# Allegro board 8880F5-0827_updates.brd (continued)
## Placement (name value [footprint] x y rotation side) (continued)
NOREF#692  -  []  277.17 288.86 0 top
NOREF#693  -  []  272.24 242.32 90 top
NOREF#694  -  []  118.99 171.65 0 top
NOREF#695  -  []  341.63 195.43 90 top
NOREF#696  -  []  310.43 188.88 0 top
NOREF#697  -  []  390.53 180.15 0 top
NOREF#698  -  []  326.23 233.13 0 top
NOREF#699  -  []  420.15 131.44 90 top
NOREF#700  -  []  352.25 182.96 0 top
NOREF#701  -  []  251.62 204.35 90 top
NOREF#702  -  []  405.93 256.92 90 top
NOREF#703  -  []  385.19 289.12 0 top
NOREF#704  -  []  501.87 276.41 90 top
NOREF#705  -  []  310.41 186.34 90 top
NOREF#706  -  []  199.59 216.47 90 top
NOREF#707  -  []  106.11 234.24 0 top
NOREF#708  -  []  229.51 246.66 0 top
NOREF#709  -  []  384.17 180.15 90 top
NOREF#710  -  []  182.57 171.96 0 top
NOREF#711  -  []  262.36 225.04 90 top
NOREF#712  -  []  201.23 229.07 90 top
NOREF#713  -  []  221.56 239.06 0 top
NOREF#714  -  []  389.7 209.36 0 top
NOREF#715  -  []  401.89 180.15 0 top
NOREF#716  -  []  265.81 296.86 0 top
NOREF#717  -  []  259.97 204.35 90 top
NOREF#718  -  []  259.33 264.35 90 top
NOREF#719  -  []  465.45 273.87 90 top
NOREF#720  -  []  423.61 182.42 90 top
NOREF#721  -  []  238.3 223.52 90 top
NOREF#722  -  []  346.69 128.87 90 top
NOREF#723  -  []  199.33 226.57 90 top
NOREF#724  -  []  352.25 185.5 0 top
NOREF#725  -  []  209.33 187.82 90 top
NOREF#726  -  []  219.81 213.69 90 top
NOREF#727  -  []  127.55 191.95 90 top
NOREF#728  -  []  380.59 287.22 0 top
NOREF#729  -  []  451.68 186.77 0 top
NOREF#730  -  []  221.56 242.89 0 top
NOREF#731  -  []  328.96 224.72 0 top
NOREF#732  -  []  331.06 223.82 90 top
NOREF#733  -  []  336.77 225.04 90 top
NOREF#734  -  []  192.57 256.4 90 top
NOREF#735  -  []  319.33 243.63 90 top
NOREF#736  -  []  340.61 286.96 90 top
NOREF#737  -  []  310.41 187.61 90 top
NOREF#738  -  []  384.36 131.89 0 top
NOREF#739  -  []  383.09 241.11 0 top
NOREF#740  -  []  395.07 129.99 0 top
NOREF#741  -  []  337.09 224.74 90 top
NOREF#742  -  []  310.43 254.01 0 top
NOREF#743  -  []  258.2 246.67 0 top
NOREF#744  -  []  184.47 165.4 90 top
NOREF#745  -  []  369.63 289.12 0 top
NOREF#746  -  []  168.13 240.88 90 top
NOREF#747  -  []  210.6 255.9 90 top
NOREF#748  -  []  317.05 288.86 0 top
NOREF#749  -  []  448.94 276.41 90 top
NOREF#750  -  []  465.45 290.38 90 top
NOREF#751  -  []  473.79 239.64 0 top
NOREF#752  -  []  226.85 271.67 0 top
NOREF#753  -  []  201.23 206.29 90 top
NOREF#754  -  []  304.65 271.67 0 top
NOREF#755  -  []  369.38 257.11 0 top
NOREF#756  -  []  332.51 264.35 90 top
NOREF#757  -  []  373.87 171.39 0 top
NOREF#758  -  []  392.47 224.3 90 top
NOREF#759  -  []  327.25 204.35 90 top
NOREF#760  -  []  396.28 180.2 90 top
NOREF#761  -  []  314.33 228.13 90 top
NOREF#762  -  []  309.05 211.67 0 top
NOREF#763  -  []  314.33 168.13 90 top
NOREF#764  -  []  240.83 254.63 0 top
NOREF#765  -  []  459.28 211.76 0 top
NOREF#766  -  []  175.8 187.82 90 top
NOREF#767  -  []  107.02 171.57 0 top
NOREF#768  -  []  333.4 264.35 90 top
NOREF#769  -  []  111.54 290.38 90 top
NOREF#770  -  []  333.4 204.35 90 top
NOREF#771  -  []  424.47 163.09 90 top
NOREF#772  -  []  246.23 173.13 0 top
NOREF#773  -  []  336.77 165.04 90 top
NOREF#774  -  []  412.24 144.98 90 top
NOREF#775  -  []  209.23 250.38 90 top
NOREF#776  -  []  374.34 210.38 90 top
NOREF#777  -  []  271.04 242.96 0 top
NOREF#778  -  []  407.71 217.61 0 top
NOREF#779  -  []  318.3 163.52 90 top
NOREF#780  -  []  175.7 154.88 90 top
NOREF#781  -  []  184.47 231.27 90 top
NOREF#782  -  []  346.27 135.17 90 top
NOREF#783  -  []  263.19 135.19 0 top
NOREF#784  -  []  409.74 180.2 90 top
NOREF#785  -  []  453.88 195.91 0 top
NOREF#786  -  []  175.8 174.36 90 top
NOREF#787  -  []  230.43 189.52 0 top
NOREF#788  -  []  230.41 193.37 90 top
NOREF#789  -  []  337.09 223.52 90 top
NOREF#790  -  []  326.17 131.69 90 top
NOREF#791  -  []  373.68 265.11 0 top
NOREF#792  -  []  259.33 205.55 0 top
NOREF#793  -  []  166.06 230.19 90 top
NOREF#794  -  []  184.89 240.88 90 top
NOREF#795  -  []  450.03 225.6 0 top
NOREF#796  -  []  478.57 257.36 90 top
NOREF#797  -  []  409.74 163.69 90 top
NOREF#798  -  []  237.57 209.63 90 top
NOREF#799  -  []  293.66 272.15 90 top
NOREF#800  -  []  313.98 131.09 90 top
NOREF#801  -  []  262.68 224.74 90 top
NOREF#802  -  []  229.51 247.93 0 top
NOREF#803  -  []  211.11 173.86 90 top
NOREF#804  -  []  167.7 255.15 90 top
NOREF#805  -  []  103.93 235.64 90 top
NOREF#806  -  []  84.04 290.38 90 top
NOREF#807  -  []  209.23 209.49 90 top
NOREF#808  -  []  315.16 290.13 90 top
NOREF#809  -  []  383.09 224.85 0 top
NOREF#810  -  []  298.49 288.91 90 top
NOREF#811  -  []  301.56 179.06 0 top
NOREF#812  -  []  318.3 224.74 90 top
NOREF#813  -  []  302.11 252.14 0 top
NOREF#814  -  []  459.28 183.57 90 top
NOREF#815  -  []  381.74 232.85 0 top
NOREF#816  -  []  177.33 242.18 90 top
NOREF#817  -  []  281.47 296.86 0 top
NOREF#818  -  []  378.33 257.11 90 top
NOREF#819  -  []  288.14 286.96 0 top
NOREF#820  -  []  459.28 227 0 top
NOREF#821  -  []  167.7 229.07 90 top
NOREF#822  -  []  257.09 223.52 90 top
NOREF#823  -  []  192.47 236.67 90 top
NOREF#824  -  []  397.8 146.33 90 top
NOREF#825  -  []  386.46 139.89 0 top
NOREF#826  -  []  463.61 222.58 0 top
NOREF#827  -  []  318.32 131.64 0 top
NOREF#828  -  []  310.43 193.37 90 top
NOREF#829  -  []  409.49 163.64 0 top
NOREF#830  -  []  398.65 273.11 0 top
NOREF#831  -  []  376.98 224.6 0 top
NOREF#832  -  []  417.2 171.64 0 top
NOREF#833  -  []  253.4 265.56 90 top
NOREF#834  -  []  192.47 264.1 90 top
NOREF#835  -  []  272.25 183.59 90 top
NOREF#836  -  []  271.04 189.18 0 top
NOREF#837  -  []  369.63 273.11 0 top
NOREF#838  -  []  296.96 252.14 0 top
NOREF#839  -  []  263.71 288.86 0 top
NOREF#840  -  []  392.24 199.18 90 top
NOREF#841  -  []  460.93 182.17 90 top
NOREF#842  -  []  184.47 190.12 90 top
NOREF#843  -  []  256.73 132.14 0 top
NOREF#844  -  []  406.52 131.89 90 top
NOREF#845  -  []  184.47 242.78 90 top
NOREF#846  -  []  115.61 191.95 0 top
NOREF#847  -  []  311.44 288.86 0 top
NOREF#848  -  []  182.57 254 0 top
NOREF#849  -  []  296.81 275.94 0 top
NOREF#850  -  []  461.96 210.36 0 top
NOREF#851  -  []  172.08 275.14 90 top
NOREF#852  -  []  175.7 148.38 90 top
NOREF#853  -  []  339.33 205.56 0 top
NOREF#854  -  []  277.5 155.38 0 top
NOREF#855  -  []  371.48 232.6 0 top
NOREF#856  -  []  248.61 290.13 90 top
NOREF#857  -  []  116.01 214.71 0 top
NOREF#858  -  []  184.47 217.55 90 top
NOREF#859  -  []  419.9 240.66 90 top
NOREF#860  -  []  184.47 186.57 0 top
NOREF#861  -  []  237.83 257.63 0 top
NOREF#862  -  []  424.98 146.33 90 top
NOREF#863  -  []  465.81 171.53 0 top
NOREF#864  -  []  468.68 129.54 0 top
NOREF#865  -  []  393.19 287.22 90 top
NOREF#866  -  []  396.55 257.37 0 top
NOREF#867  -  []  276.4 147.38 0 top
NOREF#868  -  []  168.13 159.1 90 top
NOREF#869  -  []  209.33 228.97 90 top
NOREF#870  -  []  215.96 248.49 0 top
NOREF#871  -  []  332.83 265.86 90 top
NOREF#872  -  []  326.23 173.13 0 top
NOREF#873  -  []  260.74 135.19 90 top
NOREF#874  -  []  377.48 273.16 90 top
NOREF#875  -  []  383.07 163.44 90 top
NOREF#876  -  []  318.45 197.01 0 top
NOREF#877  -  []  404.15 289.12 0 top
NOREF#878  -  []  167.7 247.18 90 top
NOREF#879  -  []  425.2 161.74 90 top
NOREF#880  -  []  118.74 210.19 90 top
NOREF#881  -  []  352.24 189.18 90 top
NOREF#882  -  []  330.49 163.52 90 top
NOREF#883  -  []  201.23 187.92 90 top
NOREF#884  -  []  247.78 140.14 0 top
NOREF#885  -  []  36.1 129.71 90 top
NOREF#886  -  []  384.36 131.89 0 top
NOREF#887  -  []  201.21 276.04 90 top
NOREF#888  -  []  373.83 192.28 0 top
NOREF#889  -  []  128.05 271.33 90 top
NOREF#890  -  []  405.93 224.56 90 top
NOREF#891  -  []  119.7 231.22 0 top
NOREF#892  -  []  272.25 189.82 0 top
NOREF#893  -  []  155.57 289.11 90 top
NOREF#894  -  []  256.45 164.74 0 top
NOREF#895  -  []  247.25 205.56 90 top
NOREF#896  -  []  298.16 248.49 0 top
NOREF#897  -  []  268.94 272.1 0 top
NOREF#898  -  []  272.24 189.18 90 top
NOREF#899  -  []  352.55 241.37 0 top
NOREF#900  -  []  419.9 240.56 90 top
NOREF#901  -  []  274.37 147.93 90 top
NOREF#902  -  []  309.05 271.67 0 top
NOREF#903  -  []  258.2 186.67 0 top
NOREF#904  -  []  253.53 140.14 0 top
NOREF#905  -  []  250.5 288.86 0 top
NOREF#906  -  []  247.57 264.65 90 top
NOREF#907  -  []  385.93 178.25 0 top
NOREF#908  -  []  309.21 193.37 0 top
NOREF#909  -  []  318.45 257.01 0 top
NOREF#910  -  []  167.7 163.2 90 top
NOREF#911  -  []  329.85 164.72 0 top
NOREF#912  -  []  351.04 245.5 0 top
NOREF#913  -  []  410.52 273.37 0 top
NOREF#914  -  []  418.12 257.42 90 top
NOREF#915  -  []  410.52 241.11 0 top
NOREF#916  -  []  306.71 131.64 0 top
NOREF#917  -  []  410.84 163.64 90 top
NOREF#918  -  []  343.31 164.74 0 top
NOREF#919  -  []  459.28 192.71 0 top
NOREF#920  -  []  392.73 171.64 0 top
NOREF#921  -  []  383.01 139.89 0 top
NOREF#922  -  []  199.33 185.42 0 top
NOREF#923  -  []  11.6 261.68 90 top
NOREF#924  -  []  331.86 252.43 90 top
NOREF#925  -  []  248.33 187.93 0 top
NOREF#926  -  []  215.96 237.06 0 top
NOREF#927  -  []  309.51 247.93 0 top
NOREF#928  -  []  424.98 146.43 90 top
NOREF#929  -  []  415.61 181.32 90 top
NOREF#930  -  []  272.25 181.05 90 top
NOREF#931  -  []  461.96 174.55 0 top
NOREF#932  -  []  404.15 257.37 0 top
NOREF#933  -  []  331.94 264.65 90 top
NOREF#934  -  []  381.2 226.12 90 top
NOREF#935  -  []  451.68 230.2 0 top
NOREF#936  -  []  331.05 205.86 90 top
NOREF#937  -  []  401.89 163.64 0 top
NOREF#938  -  []  167.7 201.89 90 top
NOREF#939  -  []  184.47 178.86 90 top
NOREF#940  -  []  184.47 214 90 top
NOREF#941  -  []  473.6 162.62 90 top
NOREF#942  -  []  184.47 241.43 0 top
NOREF#943  -  []  419.9 288.67 90 top
NOREF#944  -  []  235.85 288.61 90 top
NOREF#945  -  []  327.25 265.56 0 top
NOREF#946  -  []  461.96 166.93 0 top
NOREF#947  -  []  263.95 224.74 90 top
NOREF#948  -  []  66.26 271.33 90 top
NOREF#949  -  []  223.56 185.29 90 top
NOREF#950  -  []  310.43 186.34 0 top
NOREF#951  -  []  450.03 234.74 0 top
NOREF#952  -  []  254.29 264.35 90 top
NOREF#953  -  []  396.28 163.69 90 top
NOREF#954  -  []  329.6 224.74 90 top
NOREF#955  -  []  377.23 257.16 90 top
NOREF#956  -  []  127.59 211.59 90 top
NOREF#957  -  []  298.24 288.86 0 top
NOREF#958  -  []  300.01 288.31 90 top
NOREF#959  -  []  122.15 187.53 0 top
NOREF#960  -  []  241.6 296.61 0 top
NOREF#961  -  []  254.29 265.55 0 top
NOREF#962  -  []  322.23 233.13 90 top
NOREF#963  -  []  184.89 159.1 90 top
NOREF#964  -  []  168.13 227.17 90 top
NOREF#965  -  []  411.26 163.09 90 top
NOREF#966  -  []  398.65 257.37 0 top
NOREF#967  -  []  397.38 180.15 90 top
NOREF#968  -  []  254.61 204.65 90 top
NOREF#969  -  []  381.74 249.11 0 top
NOREF#970  -  []  209.23 222.95 90 top
NOREF#971  -  []  393.19 239.21 90 top
NOREF#972  -  []  310.43 246.34 0 top
NOREF#973  -  []  224.65 271.67 0 top
NOREF#974  -  []  209.49 148.63 90 top
NOREF#975  -  []  384.08 209.16 90 top
NOREF#976  -  []  375.73 193.43 0 top
NOREF#977  -  []  406.65 223.21 90 top
NOREF#978  -  []  221.87 295.91 0 top
NOREF#979  -  []  473.79 239.64 0 top
NOREF#980  -  []  167.7 233.47 90 top
NOREF#981  -  []  351.04 184.23 0 top
NOREF#982  -  []  409.43 139.89 0 top
NOREF#983  -  []  177.33 160.4 90 top
NOREF#984  -  []  229.21 246.34 0 top
NOREF#985  -  []  184.47 219.75 90 top
NOREF#986  -  []  201.23 233.47 90 top
NOREF#987  -  []  330.49 224.74 90 top
NOREF#988  -  []  369.38 224.6 0 top
NOREF#989  -  []  110.21 214.71 0 top
NOREF#990  -  []  501.87 273.87 90 top
NOREF#991  -  []  310.43 253.37 90 top
NOREF#992  -  []  408.02 287.22 0 top
NOREF#993  -  []  334.29 265.55 0 top
NOREF#994  -  []  167.7 227.72 90 top
NOREF#995  -  []  223.15 271.32 90 top
NOREF#996  -  []  346.27 130.77 90 top
NOREF#997  -  []  265.39 135.19 0 top
NOREF#998  -  []  337.09 163.52 90 top
NOREF#999  -  []  94.93 190.55 0 top
NOREF#1000  -  []  301.34 286.96 0 top
NOREF#1001  -  []  331.22 193.63 0 top
NOREF#1002  -  []  404.4 225.16 90 top
NOREF#1003  -  []  295.96 248.49 0 top
NOREF#1004  -  []  456.08 239.34 0 top
NOREF#1005  -  []  252.83 204.65 90 top
NOREF#1006  -  []  221.56 231.46 0 top
NOREF#1007  -  []  107.02 179.19 0 top
NOREF#1008  -  []  199.59 158.5 90 top
NOREF#1009  -  []  406.94 131.34 90 top
NOREF#1010  -  []  317.05 288.86 0 top
NOREF#1011  -  []  208.98 257.6 90 top
NOREF#1012  -  []  468.01 179.15 0 top
NOREF#1013  -  []  201.23 204.09 90 top
NOREF#1014  -  []  327.25 265.56 90 top
NOREF#1015  -  []  222.11 192.14 0 top
NOREF#1016  -  []  388.43 163.64 0 top
NOREF#1017  -  []  392.04 289.12 90 top
NOREF#1018  -  []  273.95 147.38 90 top
NOREF#1019  -  []  310.43 186.34 90 top
NOREF#1020  -  []  124.35 195.15 0 top
NOREF#1021  -  []  271.56 288.91 90 top
NOREF#1022  -  []  408.63 290.39 90 top
NOREF#1023  -  []  462.06 277.31 90 top
NOREF#1024  -  []  415.6 146.88 0 top
NOREF#1025  -  []  251.62 205.56 90 top
NOREF#1026  -  []  268.01 296.86 0 top
NOREF#1027  -  []  127.81 175.44 90 top
NOREF#1028  -  []  470.71 227 90 top
NOREF#1029  -  []  120.21 178.64 0 top
NOREF#1030  -  []  261.63 195.43 90 top
NOREF#1031  -  []  127.7 238.84 0 top
NOREF#1032  -  []  192.57 201.79 90 top
NOREF#1033  -  []  394.66 290.39 90 top
NOREF#1034  -  []  165.8 226.57 0 top
NOREF#1035  -  []  101.29 247.16 90 top
NOREF#1036  -  []  251.05 265.86 90 top
NOREF#1037  -  []  192.47 222.95 90 top
NOREF#1038  -  []  271.04 189.82 0 top
NOREF#1039  -  []  104.18 191.95 90 top
NOREF#1040  -  []  108.27 171.02 0 top
NOREF#1041  -  []  167.7 192.32 90 top
NOREF#1042  -  []  165.8 131.57 90 top
NOREF#1043  -  []  339.33 265.56 90 top
NOREF#1044  -  []  239.4 296.61 0 top
NOREF#1045  -  []  237.98 165.04 90 top
NOREF#1046  -  []  251.62 265.56 0 top
NOREF#1047  -  []  329.6 223.52 90 top
NOREF#1048  -  []  390.34 192.28 90 top
NOREF#1049  -  []  449.99 217.9 0 top
NOREF#1050  -  []  459.24 175.86 0 top
NOREF#1051  -  []  381.2 242.38 90 top
NOREF#1052  -  []  382.47 133.16 90 top
NOREF#1053  -  []  393.74 131.44 90 top
NOREF#1054  -  []  385.19 232.85 0 top
NOREF#1055  -  []  396.55 273.11 0 top
NOREF#1056  -  []  309.51 187.93 0 top
NOREF#1057  -  []  399.39 161.74 0 top
NOREF#1058  -  []  397.8 163.09 90 top
NOREF#1059  -  []  172.08 272.6 90 top
NOREF#1060  -  []  331.38 164.74 90 top
NOREF#1061  -  []  448.94 290.38 90 top
NOREF#1062  -  []  286.12 288.86 90 top
NOREF#1063  -  []  383.83 209.11 0 top
NOREF#1064  -  []  194.09 255.9 90 top
NOREF#1065  -  []  201.23 227.72 0 top
NOREF#1066  -  []  461.96 217.98 0 top
NOREF#1067  -  []  306.27 156.63 90 top
NOREF#1068  -  []  328.01 286.96 0 top
NOREF#1069  -  []  386.46 131.89 0 top
NOREF#1070  -  []  559.43 297.18 90 top
NOREF#1071  -  []  384.59 162.94 90 top
NOREF#1072  -  []  118.96 179.19 0 top
NOREF#1073  -  []  309.21 248.88 0 top
NOREF#1074  -  []  393.31 131.89 90 top
NOREF#1075  -  []  401.89 163.64 0 top
NOREF#1076  -  []  184.89 213.45 90 top
NOREF#1077  -  []  295.96 188.49 0 top
NOREF#1078  -  []  375.22 163.39 0 top
NOREF#1079  -  []  254.29 265.56 0 top
NOREF#1080  -  []  167.7 178.86 90 top
NOREF#1081  -  []  511.59 257.36 90 top
NOREF#1082  -  []  310.43 243.09 90 top
NOREF#1083  -  []  390.69 224.85 0 top
NOREF#1084  -  []  107.18 246.83 90 top
NOREF#1085  -  []  175.7 164.3 90 top
NOREF#1086  -  []  175.7 168.6 90 top
NOREF#1087  -  []  115.61 211.51 90 top
NOREF#1088  -  []  302.11 129.74 0 top
NOREF#1089  -  []  351.34 189.5 0 top
NOREF#1090  -  []  450.03 225.6 0 top
NOREF#1091  -  []  302.71 132.91 90 top
NOREF#1092  -  []  277.17 288.86 0 top
NOREF#1093  -  []  296.96 192.14 0 top
NOREF#1094  -  []  258.61 131.69 90 top
NOREF#1095  -  []  339.89 288.31 90 top
NOREF#1096  -  []  167.7 233.47 90 top
NOREF#1097  -  []  240.94 151.63 90 top
NOREF#1098  -  []  310.43 253.37 0 top
NOREF#1099  -  []  375.73 193.43 90 top
NOREF#1100  -  []  118.45 239.39 0 top
NOREF#1101  -  []  295.96 237.06 0 top
NOREF#1102  -  []  331.38 223.52 90 top
NOREF#1103  -  []  298.16 237.06 0 top
NOREF#1104  -  []  339.33 265.56 0 top
NOREF#1105  -  []  237.66 224.72 0 top
NOREF#1106  -  []  253.4 264.35 90 top
NOREF#1107  -  []  482.64 235.89 90 top
NOREF#1108  -  []  310.73 253.69 0 top
NOREF#1109  -  []  329.28 165.04 90 top
NOREF#1110  -  []  185.2 290.01 90 top
NOREF#1111  -  []  314.2 145.6 90 top
NOREF#1112  -  []  155.57 291.65 90 top
NOREF#1113  -  []  167.7 206.29 90 top
NOREF#1114  -  []  318.32 131.64 0 top
NOREF#1115  -  []  249.85 164.72 0 top
NOREF#1116  -  []  217.71 276.09 0 top
NOREF#1117  -  []  450.03 191.31 0 top
NOREF#1118  -  []  192.47 205.19 90 top
NOREF#1119  -  []  167.7 219.75 90 top
NOREF#1120  -  []  166.06 162.12 90 top
NOREF#1121  -  []  352.25 242.32 90 top
NOREF#1122  -  []  319.33 183.63 90 top
NOREF#1123  -  []  112.67 171.02 0 top
NOREF#1124  -  []  399.07 208.91 90 top
NOREF#1125  -  []  336.45 224.74 0 top
NOREF#1126  -  []  424.47 163.19 90 top
NOREF#1127  -  []  208.98 264.1 90 top
NOREF#1128  -  []  344.62 131.89 90 top
NOREF#1129  -  []  400.24 195.88 90 top
NOREF#1130  -  []  175.7 230.17 90 top
NOREF#1131  -  []  216.96 240.71 0 top
NOREF#1132  -  []  271.34 189.5 0 top
NOREF#1133  -  []  251.06 223.82 90 top
NOREF#1134  -  []  194.09 228.47 90 top
NOREF#1135  -  []  393.74 131.34 90 top
NOREF#1136  -  []  465.81 222.58 0 top
NOREF#1137  -  []  398.65 225.11 0 top
NOREF#1138  -  []  242.23 173.13 0 top
NOREF#1139  -  []  300.74 286.96 90 top
NOREF#1140  -  []  250.5 288.86 0 top
NOREF#1141  -  []  250.73 205.56 0 top
NOREF#1142  -  []  262.68 223.52 90 top
NOREF#1143  -  []  405.5 225.11 90 top
NOREF#1144  -  []  330.73 265.55 0 top
NOREF#1145  -  []  275.82 296.86 0 top
NOREF#1146  -  []  118.74 215.34 0 top
NOREF#1147  -  []  103.93 235.64 0 top
NOREF#1148  -  []  98.53 238.84 0 top
NOREF#1149  -  []  250.73 265.55 0 top
NOREF#1150  -  []  368.03 265.11 0 top
NOREF#1151  -  []  463.11 186.77 0 top
NOREF#1152  -  []  340.83 174.63 90 top
NOREF#1153  -  []  378.58 289.12 90 top
NOREF#1154  -  []  251.94 264.65 90 top
NOREF#1155  -  []  272.25 182.32 90 top
NOREF#1156  -  []  450.03 210.36 0 top
NOREF#1157  -  []  166.06 203.01 90 top
NOREF#1158  -  []  405.93 240.66 90 top
NOREF#1159  -  []  342.04 164.74 0 top
NOREF#1160  -  []  471.21 168.33 90 top
NOREF#1161  -  []  403.99 163.64 0 top
NOREF#1162  -  []  333.72 204.65 90 top
NOREF#1163  -  []  367.48 225.87 90 top
NOREF#1164  -  []  124.35 222.33 0 top
NOREF#1165  -  []  230.43 253.37 0 top
NOREF#1166  -  []  167.7 176.66 90 top
NOREF#1167  -  []  175.7 236.67 90 top
NOREF#1168  -  []  290.64 288.86 0 top
NOREF#1169  -  []  271.34 242.64 0 top
NOREF#1170  -  []  239.33 243.63 90 top
NOREF#1171  -  []  251.94 204.65 90 top
NOREF#1172  -  []  306.92 146.05 0 top
NOREF#1173  -  []  342.36 225.04 90 top
NOREF#1174  -  []  388.35 217.36 0 top
NOREF#1175  -  []  377.23 289.12 0 top
NOREF#1176  -  []  332.51 204.35 90 top
NOREF#1177  -  []  184.47 215.35 90 top
NOREF#1178  -  []  199.33 226.57 0 top
NOREF#1179  -  []  331.94 265.86 90 top
NOREF#1180  -  []  217.71 216.09 0 top
NOREF#1181  -  []  367.73 290.39 90 top
NOREF#1182  -  []  373.68 232.6 0 top
NOREF#1183  -  []  369.63 289.12 0 top
NOREF#1184  -  []  310.43 243.09 0 top
NOREF#1185  -  []  308.36 262.16 45 top
NOREF#1186  -  []  112.67 178.64 0 top
NOREF#1187  -  []  352.25 182.32 90 top
NOREF#1188  -  []  230.73 189.2 0 top
NOREF#1189  -  []  408.63 274.64 90 top
NOREF#1190  -  []  511.59 276.41 90 top
NOREF#1191  -  []  485.36 259.9 90 top
NOREF#1192  -  []  412.62 241.11 0 top
NOREF#1193  -  []  184.47 233.47 90 top
NOREF#1194  -  []  241.82 227.13 90 top
NOREF#1195  -  []  478.57 259.9 90 top
NOREF#1196  -  []  305.94 296.86 0 top
NOREF#1197  -  []  456.08 195.91 0 top
NOREF#1198  -  []  175.7 202.99 90 top
NOREF#1199  -  []  418.38 131.89 0 top
NOREF#1200  -  []  167.7 231.27 90 top
NOREF#1201  -  []  192.47 218.65 90 top
NOREF#1202  -  []  201.66 199.99 90 top
NOREF#1203  -  []  405.93 240.56 90 top
NOREF#1204  -  []  388.43 180.15 0 top
NOREF#1205  -  []  192.47 209.49 90 top
NOREF#1206  -  []  377.23 273.11 0 top
NOREF#1207  -  []  394.05 223.21 0 top
NOREF#1208  -  []  461.86 182.17 90 top
NOREF#1209  -  []  375.22 180.15 0 top
NOREF#1210  -  []  166.06 189.04 90 top
NOREF#1211  -  []  167.7 161 90 top
NOREF#1212  -  []  327.7 131.09 90 top
NOREF#1213  -  []  382.82 180.15 0 top
NOREF#1214  -  []  341.63 255.43 90 top
NOREF#1215  -  []  122.15 222.33 0 top
NOREF#1216  -  []  419.64 256.82 90 top
NOREF#1217  -  []  381.74 281.11 0 top
NOREF#1218  -  []  118.99 171.65 0 top
NOREF#1219  -  []  184.47 201.89 90 top
NOREF#1220  -  []  317.66 224.72 0 top
NOREF#1221  -  []  223.56 233.86 90 top
NOREF#1222  -  []  333.4 265.56 0 top
NOREF#1223  -  []  230.41 243.09 90 top
NOREF#1224  -  []  250.74 164.74 0 top
NOREF#1225  -  []  456.04 179.06 0 top
NOREF#1226  -  []  237.66 164.72 0 top
NOREF#1227  -  []  338.11 288.86 0 top
NOREF#1228  -  []  201.21 273.5 90 top
NOREF#1229  -  []  341.63 173.83 90 top
NOREF#1230  -  []  250.5 288.86 0 top
NOREF#1231  -  []  108.27 171.02 0 top
NOREF#1232  -  []  310.41 248.88 90 top
NOREF#1233  -  []  352.24 181.05 90 top
NOREF#1234  -  []  215.96 188.49 0 top
NOREF#1235  -  []  405.93 256.82 90 top
NOREF#1236  -  []  175.7 191.22 90 top
NOREF#1237  -  []  400.54 171.64 0 top
NOREF#1238  -  []  259.88 288.41 90 top
NOREF#1239  -  []  402.14 146.88 0 top
NOREF#1240  -  []  373.32 181.42 90 top
NOREF#1241  -  []  339.33 205.55 0 top
NOREF#1242  -  []  232.25 211.67 90 top
NOREF#1243  -  []  450.03 234.74 0 top
NOREF#1244  -  []  96.58 195.15 0 top
NOREF#1245  -  []  339.97 264.35 90 top
NOREF#1246  -  []  309.51 189.2 0 top
NOREF#1247  -  []  260.74 143.19 0 top
NOREF#1248  -  []  124.64 171.1 0 top
NOREF#1249  -  []  314.71 129.74 90 top
NOREF#1250  -  []  396.55 241.11 0 top
NOREF#1251  -  []  304.82 146.05 0 top
NOREF#1252  -  []  182.57 199.39 0 top
NOREF#1253  -  []  343.31 164.72 0 top
NOREF#1254  -  []  379 272.56 90 top
NOREF#1255  -  []  251.38 163.52 90 top
NOREF#1256  -  []  192.47 232.37 90 top
NOREF#1257  -  []  351.04 185.5 0 top
NOREF#1258  -  []  272.55 241.37 0 top
NOREF#1259  -  []  253.4 265.55 0 top
NOREF#1260  -  []  470.79 128.27 0 top
NOREF#1261  -  []  253.72 205.86 90 top
NOREF#1262  -  []  258.1 288.86 0 top
NOREF#1263  -  []  118.7 190.55 90 top
NOREF#1264  -  []  247.34 133.41 90 top
NOREF#1265  -  []  242.23 233.13 0 top
NOREF#1266  -  []  192.47 250.38 90 top
NOREF#1267  -  []  167.7 200.54 90 top
NOREF#1268  -  []  451.64 222.5 0 top
NOREF#1269  -  []  366.88 239.21 0 top
NOREF#1270  -  []  314.92 144.15 90 top
NOREF#1271  -  []  331.62 265.56 90 top
NOREF#1272  -  []  105.93 204.27 90 top
NOREF#1273  -  []  209.23 205.19 90 top
NOREF#1274  -  []  404.15 241.11 0 top
NOREF#1275  -  []  481.96 276.41 90 top
NOREF#1276  -  []  371.73 281.11 0 top
NOREF#1277  -  []  460.93 166.93 90 top
NOREF#1278  -  []  252.51 204.35 90 top
NOREF#1279  -  []  215.96 248.49 0 top
NOREF#1280  -  []  251.05 204.65 90 top
NOREF#1281  -  []  262.04 224.72 0 top
NOREF#1282  -  []  263.63 223.82 90 top
NOREF#1283  -  []  409.49 180.15 0 top
NOREF#1284  -  []  201.23 244.98 90 top
NOREF#1285  -  []  251.05 205.86 90 top
NOREF#1286  -  []  398.65 209.36 90 top
NOREF#1287  -  []  165.8 199.39 0 top
NOREF#1288  -  []  339.46 288.86 90 top
NOREF#1289  -  []  337.9 186.35 90 top
NOREF#1290  -  []  453.84 179.06 0 top
NOREF#1291  -  []  397.57 131.89 0 top
NOREF#1292  -  []  215.96 177.06 0 top
NOREF#1293  -  []  331.94 205.86 90 top
NOREF#1294  -  []  167.7 190.12 90 top
NOREF#1295  -  []  399.67 131.89 0 top
NOREF#1296  -  []  165.8 254 0 top
NOREF#1297  -  []  184.47 241.43 90 top
NOREF#1298  -  []  405.51 217.61 0 top
NOREF#1299  -  []  271.31 288.86 0 top
NOREF#1300  -  []  351.34 241.37 0 top
NOREF#1301  -  []  387.2 207.46 0 top
NOREF#1302  -  []  459.28 236.14 90 top
NOREF#1303  -  []  247.57 204.65 90 top
NOREF#1304  -  []  384.59 162.84 90 top
NOREF#1305  -  []  107.02 174.04 90 top
NOREF#1306  -  []  113.08 129.54 0 top
NOREF#1307  -  []  124.39 214.79 0 top
NOREF#1308  -  []  119.95 222.33 0 top
NOREF#1309  -  []  376.98 241.11 0 top
NOREF#1310  -  []  304.61 131.64 0 top
NOREF#1311  -  []  230.43 187.61 90 top
NOREF#1312  -  []  398.65 265.37 0 top
NOREF#1313  -  []  271.04 181.69 0 top
NOREF#1314  -  []  332.61 296.86 0 top
NOREF#1315  -  []  401.89 163.64 0 top
NOREF#1316  -  []  352.25 245.5 0 top
NOREF#1317  -  []  460.93 210.36 90 top
NOREF#1318  -  []  254.8 296.86 0 top
NOREF#1319  -  []  230.73 189.2 0 top
NOREF#1320  -  []  259.33 265.56 90 top
NOREF#1321  -  []  175.7 264.1 90 top
NOREF#1322  -  []  201.66 227.17 90 top
NOREF#1323  -  []  390.94 289.17 90 top
NOREF#1324  -  []  379.48 222.7 90 top
NOREF#1325  -  []  271.34 185.18 0 top
NOREF#1326  -  []  351.04 249.18 0 top
NOREF#1327  -  []  75.98 273.87 90 top
NOREF#1328  -  []  303.56 245.29 90 top
NOREF#1329  -  []  333.72 265.86 90 top
NOREF#1330  -  []  397.8 179.7 90 top
NOREF#1331  -  []  192.47 175.56 90 top
NOREF#1332  -  []  387.39 281.11 0 top
NOREF#1333  -  []  235.4 289.88 90 top
NOREF#1334  -  []  333.72 264.65 90 top
NOREF#1335  -  []  352.24 249.18 90 top
NOREF#1336  -  []  352.25 184.86 90 top
NOREF#1337  -  []  263.14 282 0 top
NOREF#1338  -  []  251.22 253.63 0 top
NOREF#1339  -  []  192.57 242.68 90 top
NOREF#1340  -  []  251.22 193.63 0 top
NOREF#1341  -  []  415.61 179.97 90 top
NOREF#1342  -  []  420.62 271.47 90 top
NOREF#1343  -  []  175.7 250.38 90 top
NOREF#1344  -  []  225.83 264.31 0 top
NOREF#1345  -  []  385.93 144.98 0 top
NOREF#1346  -  []  317.98 165.04 90 top
NOREF#1347  -  []  250.17 223.82 90 top
NOREF#1348  -  []  461.96 166.93 0 top
NOREF#1349  -  []  375.73 199.18 90 top
NOREF#1350  -  []  372.72 178.25 0 top
NOREF#1351  -  []  199.33 257.62 90 top
NOREF#1352  -  []  408.02 239.21 0 top
NOREF#1353  -  []  175.7 177.76 90 top
NOREF#1354  -  []  230.41 183.09 90 top
NOREF#1355  -  []  118.45 231.77 0 top
NOREF#1356  -  []  295.96 177.06 0 top
NOREF#1357  -  []  250.73 205.55 0 top
NOREF#1358  -  []  471.21 175.95 0 top
NOREF#1359  -  []  250.49 224.74 90 top
NOREF#1360  -  []  175.7 246.08 90 top
NOREF#1361  -  []  299.81 213.69 90 top
NOREF#1362  -  []  166.06 257.62 90 top
NOREF#1363  -  []  115.36 235.64 90 top
NOREF#1364  -  []  465.81 214.96 0 top
NOREF#1365  -  []  199.59 171.96 90 top
NOREF#1366  -  []  228.36 202.16 45 top
NOREF#1367  -  []  167.7 241.43 90 top
NOREF#1368  -  []  275.3 155.38 0 top
NOREF#1369  -  []  385.19 273.11 0 top
NOREF#1370  -  []  309.21 247.61 0 top
NOREF#1371  -  []  423.61 184.62 90 top
NOREF#1372  -  []  200.98 260.9 90 top
NOREF#1373  -  []  398.65 249.11 0 top
NOREF#1374  -  []  66.26 273.87 90 top
NOREF#1375  -  []  352.25 244.86 90 top
NOREF#1376  -  []  390.34 192.28 0 top
NOREF#1377  -  []  309.51 243.41 0 top
NOREF#1378  -  []  343.31 224.72 0 top
NOREF#1379  -  []  75.98 271.33 90 top
NOREF#1380  -  []  167.7 173.11 90 top
NOREF#1381  -  []  298.13 214.06 90 top
NOREF#1382  -  []  380.59 222.95 0 top
NOREF#1383  -  []  352.55 245.18 0 top
NOREF#1384  -  []  387.39 249.11 0 top
NOREF#1385  -  []  467.51 186.77 0 top
NOREF#1386  -  []  184.47 151.68 90 top
NOREF#1387  -  []  314.19 145.5 90 top
NOREF#1388  -  []  292.74 296.86 0 top
NOREF#1389  -  []  209.59 147.43 90 top
NOREF#1390  -  []  338.36 288.91 90 top
NOREF#1391  -  []  406.19 171.64 0 top
NOREF#1392  -  []  288.74 290.13 90 top
NOREF#1393  -  []  386.53 164.91 90 top
NOREF#1394  -  []  175.8 160.9 90 top
NOREF#1395  -  []  116.27 178.64 0 top
NOREF#1396  -  []  395.67 133.16 90 top
NOREF#1397  -  []  249.28 163.82 90 top
NOREF#1398  -  []  334.29 205.56 0 top
NOREF#1399  -  []  209.49 175.56 90 top
NOREF#1400  -  []  475.04 195.66 0 top
NOREF#1401  -  []  352.25 189.18 90 top
NOREF#1402  -  []  230.43 193.37 90 top
NOREF#1403  -  []  387.08 188.15 0 top
NOREF#1404  -  []  396.03 163.64 0 top
NOREF#1405  -  []  371.48 249.11 0 top
NOREF#1406  -  []  310.73 186.66 0 top
NOREF#1407  -  []  395.2 233.11 0 top
NOREF#1408  -  []  240.94 211.63 90 top
NOREF#1409  -  []  408.37 258.64 90 top
NOREF#1410  -  []  385.19 249.11 0 top
NOREF#1411  -  []  168.13 132.17 90 top
NOREF#1412  -  []  327.25 265.55 0 top
NOREF#1413  -  []  339.65 204.65 90 top
NOREF#1414  -  []  175.7 216.45 90 top
NOREF#1415  -  []  262.68 163.52 90 top
NOREF#1416  -  []  257.9 246.99 0 top
NOREF#1417  -  []  411.26 179.7 90 top
NOREF#1418  -  []  230.43 183.09 90 top
NOREF#1419  -  []  175.7 150.58 90 top
NOREF#1420  -  []  473.6 206.05 90 top
NOREF#1421  -  []  229.21 253.37 0 top
NOREF#1422  -  []  478.57 291.28 90 top
NOREF#1423  -  []  226.27 156.63 90 top
NOREF#1424  -  []  115.19 128.27 0 top
NOREF#1425  -  []  249.85 164.74 0 top
NOREF#1426  -  []  239.33 236.03 0 top
NOREF#1427  -  []  217.41 273.24 90 top
NOREF#1428  -  []  310.43 183.09 0 top
NOREF#1429  -  []  420.62 239.21 90 top
NOREF#1430  -  []  312.25 271.67 90 top
NOREF#1431  -  []  326.43 288.41 90 top
NOREF#1432  -  []  118.96 179.19 0 top
NOREF#1433  -  []  310.43 249.52 0 top
NOREF#1434  -  []  272.55 189.5 0 top
NOREF#1435  -  []  238.3 164.74 90 top
NOREF#1436  -  []  201.66 186.02 90 top
NOREF#1437  -  []  271.04 182.96 0 top
NOREF#1438  -  []  192.47 177.76 90 top
NOREF#1439  -  []  184.47 147.28 90 top
NOREF#1440  -  []  270.04 280.1 0 top
NOREF#1441  -  []  165.8 240.28 0 top
NOREF#1442  -  []  250.23 132.14 0 top
NOREF#1443  -  []  230.73 183.41 0 top
NOREF#1444  -  []  369.38 241.11 0 top
NOREF#1445  -  []  310.43 248.88 90 top
NOREF#1446  -  []  177.33 201.29 90 top
NOREF#1447  -  []  238.45 197.01 0 top
NOREF#1448  -  []  449.99 217.9 0 top
NOREF#1449  -  []  279.7 155.38 0 top
NOREF#1450  -  []  397.57 131.89 0 top
NOREF#1451  -  []  184.47 255.15 0 top
NOREF#1452  -  []  201.49 146.18 0 top
NOREF#1453  -  []  240.5 288.61 0 top
NOREF#1454  -  []  385.93 161.74 0 top
NOREF#1455  -  []  201.49 159.65 0 top
NOREF#1456  -  []  200.98 255.15 0 top
NOREF#1457  -  []  301.56 182.89 0 top
NOREF#1458  -  []  192.47 216.45 90 top
NOREF#1459  -  []  406.65 239.21 90 top
NOREF#1460  -  []  175.7 257.6 90 top
NOREF#1461  -  []  337.9 246.35 90 top
NOREF#1462  -  []  383.09 257.11 0 top
NOREF#1463  -  []  330.73 204.35 90 top
NOREF#1464  -  []  234.7 298.51 0 top
NOREF#1465  -  []  228.36 262.16 45 top
NOREF#1466  -  []  112.41 195.15 0 top
NOREF#1467  -  []  378.75 240.66 90 top
NOREF#1468  -  []  390.94 257.16 90 top
NOREF#1469  -  []  119.99 214.79 0 top
NOREF#1470  -  []  390.94 224.9 90 top
NOREF#1471  -  []  269.69 135.19 0 top
NOREF#1472  -  []  184.47 192.32 90 top
NOREF#1473  -  []  391.8 217.36 0 top
NOREF#1474  -  []  402.14 146.88 0 top
NOREF#1475  -  []  383.07 180.2 90 top
NOREF#1476  -  []  341.63 233.83 90 top
NOREF#1477  -  []  124.61 178.64 0 top
NOREF#1478  -  []  310.43 247.61 0 top
NOREF#1479  -  []  336.45 164.74 0 top
NOREF#1480  -  []  272.24 241.05 90 top
NOREF#1481  -  []  122.44 171.1 0 top
NOREF#1482  -  []  342.36 163.82 90 top
NOREF#1483  -  []  418.63 131.94 90 top
NOREF#1484  -  []  230.73 186.66 0 top
NOREF#1485  -  []  271.34 245.18 0 top
NOREF#1486  -  []  330.73 205.56 90 top
NOREF#1487  -  []  319.33 236.03 90 top
NOREF#1488  -  []  473.79 191.06 90 top
NOREF#1489  -  []  251.06 225.04 90 top
NOREF#1490  -  []  423.61 188.92 90 top
NOREF#1491  -  []  250.73 205.56 90 top
NOREF#1492  -  []  300.36 237.06 0 top
NOREF#1493  -  []  351.34 189.5 0 top
NOREF#1494  -  []  296.96 180.71 0 top
NOREF#1495  -  []  412.62 297.12 0 top
NOREF#1496  -  []  303.56 185.29 90 top
NOREF#1497  -  []  251.94 265.86 90 top
NOREF#1498  -  []  192.47 191.22 90 top
NOREF#1499  -  []  167.7 204.09 90 top
NOREF#1500  -  []  289.29 296.86 0 top
NOREF#1501  -  []  265.81 288.86 0 top
NOREF#1502  -  []  199.59 145.03 0 top
NOREF#1503  -  []  343.63 225.04 90 top
NOREF#1504  -  []  116.27 171.02 0 top
NOREF#1505  -  []  106.11 234.24 0 top
NOREF#1506  -  []  118.7 188.08 0 top
NOREF#1507  -  []  167.7 132.72 90 top
NOREF#1508  -  []  392.04 224.85 90 top
NOREF#1509  -  []  463.61 179.15 0 top
NOREF#1510  -  []  167.7 186.57 0 top
NOREF#1511  -  []  305.94 288.86 0 top
NOREF#1512  -  []  343.63 165.04 90 top
NOREF#1513  -  []  223.15 211.32 90 top
NOREF#1514  -  []  251.54 252.73 90 top
NOREF#1515  -  []  392.24 193.43 0 top
NOREF#1516  -  []  301.56 239.06 0 top
NOREF#1517  -  []  118.33 271.33 90 top
NOREF#1518  -  []  394.05 271.21 0 top
NOREF#1519  -  []  383.09 289.12 0 top
NOREF#1520  -  []  110.21 195.15 0 top
NOREF#1521  -  []  253.33 241.33 90 top
NOREF#1522  -  []  262.36 296.86 0 top
NOREF#1523  -  []  192.57 147.18 90 top
NOREF#1524  -  []  478.57 277.31 90 top
NOREF#1525  -  []  122.41 178.64 0 top
NOREF#1526  -  []  201.23 186.57 90 top
NOREF#1527  -  []  481.96 273.87 90 top
NOREF#1528  -  []  375.22 163.39 0 top
NOREF#1529  -  []  247.57 265.86 90 top
NOREF#1530  -  []  317.98 163.82 90 top
NOREF#1531  -  []  420.88 129.99 90 top
NOREF#1532  -  []  309.51 249.2 0 top
NOREF#1533  -  []  287.27 286.96 90 top
NOREF#1534  -  []  165.8 158.5 90 top
NOREF#1535  -  []  290.11 280.1 0 top
NOREF#1536  -  []  283.21 270.2 90 top
NOREF#1537  -  []  339.65 204.65 90 top
NOREF#1538  -  []  247.25 265.56 0 top
NOREF#1539  -  []  184.47 204.09 90 top
NOREF#1540  -  []  343.63 163.82 90 top
NOREF#1541  -  []  184.47 151.68 90 top
NOREF#1542  -  []  403.99 171.64 0 top
NOREF#1543  -  []  230.73 193.69 0 top
NOREF#1544  -  []  248.21 132.69 90 top
NOREF#1545  -  []  330.73 265.56 90 top
NOREF#1546  -  []  397.8 146.43 90 top
NOREF#1547  -  []  201.23 192.32 90 top
NOREF#1548  -  []  415.61 185.72 90 top
NOREF#1549  -  []  383.73 202.38 90 top
NOREF#1550  -  []  477.24 239.09 0 top
NOREF#1551  -  []  331.38 163.52 90 top
NOREF#1552  -  []  251.86 252.43 90 top
NOREF#1553  -  []  177.33 228.47 90 top
NOREF#1554  -  []  372.72 161.49 0 top
NOREF#1555  -  []  461.86 230.75 0 top
NOREF#1556  -  []  250.49 163.52 90 top
NOREF#1557  -  []  327.57 264.65 90 top
NOREF#1558  -  []  393.19 222.95 90 top
NOREF#1559  -  []  310.43 246.34 90 top
NOREF#1560  -  []  392.47 240.66 90 top
NOREF#1561  -  []  237.66 164.74 0 top
NOREF#1562  -  []  392.47 272.66 90 top
NOREF#1563  -  []  302.11 240.71 0 top
NOREF#1564  -  []  465.81 179.15 0 top
NOREF#1565  -  []  456.08 186.77 0 top
NOREF#1566  -  []  258.35 288.91 90 top
NOREF#1567  -  []  184.47 186.57 90 top
NOREF#1568  -  []  261.63 255.43 90 top
NOREF#1569  -  []  286.55 288.31 90 top
NOREF#1570  -  []  230.73 187.93 0 top
NOREF#1571  -  []  167.7 151.68 90 top
NOREF#1572  -  []  175.8 133.97 90 top
NOREF#1573  -  []  254.29 265.56 90 top
NOREF#1574  -  []  201.49 147.53 90 top
NOREF#1575  -  []  252.83 264.65 90 top
NOREF#1576  -  []  377.32 180.15 0 top
NOREF#1577  -  []  367.48 258.38 90 top
NOREF#1578  -  []  309.21 243.09 0 top
NOREF#1579  -  []  456.08 171.53 0 top
NOREF#1580  -  []  297.41 213.24 90 top
NOREF#1581  -  []  380.59 239.21 0 top
NOREF#1582  -  []  419.65 256.92 90 top
NOREF#1583  -  []  271.04 185.5 0 top
NOREF#1584  -  []  229.51 193.69 0 top
NOREF#1585  -  []  329.16 296.86 0 top
NOREF#1586  -  []  373.93 297.12 0 top
NOREF#1587  -  []  414.57 265.37 0 top
NOREF#1588  -  []  165.8 226.57 90 top
NOREF#1589  -  []  101.82 290.38 90 top
NOREF#1590  -  []  251.94 205.86 90 top
NOREF#1591  -  []  251.54 192.73 90 top
NOREF#1592  -  []  209.23 195.52 90 top
NOREF#1593  -  []  119.7 238.84 0 top
NOREF#1594  -  []  199.59 243.9 90 top
NOREF#1595  -  []  257.08 132.19 90 top
NOREF#1596  -  []  229.51 249.2 0 top
NOREF#1597  -  []  415.6 146.88 0 top
NOREF#1598  -  []  401.52 210.88 90 top
NOREF#1599  -  []  451.68 239.34 0 top
NOREF#1600  -  []  465.31 230.2 0 top
NOREF#1601  -  []  272.25 249.18 90 top
NOREF#1602  -  []  252.51 265.55 0 top
NOREF#1603  -  []  209.59 174.36 90 top
NOREF#1604  -  []  217.41 273.24 0 top
NOREF#1605  -  []  352.24 242.32 90 top
NOREF#1606  -  []  94.93 190.55 0 top
NOREF#1607  -  []  308.91 139.64 0 top
NOREF#1608  -  []  298.16 188.49 0 top
NOREF#1609  -  []  333.4 205.56 90 top
NOREF#1610  -  []  301.56 171.46 0 top
NOREF#1611  -  []  309.51 246.66 0 top
NOREF#1612  -  []  182.57 212.85 90 top
NOREF#1613  -  []  400.54 188.15 0 top
NOREF#1614  -  []  298.13 274.06 90 top
NOREF#1615  -  []  119.95 195.15 0 top
NOREF#1616  -  []  330.51 288.86 0 top
NOREF#1617  -  []  325.92 131.64 0 top
NOREF#1618  -  []  406.95 131.44 90 top
NOREF#1619  -  []  395.2 297.12 0 top
NOREF#1620  -  []  385.32 161.49 90 top
NOREF#1621  -  []  175.7 182.06 90 top
NOREF#1622  -  []  251.05 264.65 90 top
NOREF#1623  -  []  209.23 189.02 90 top
NOREF#1624  -  []  184.47 145.93 90 top
NOREF#1625  -  []  229.51 189.2 0 top
NOREF#1626  -  []  343.98 288.86 0 top
NOREF#1627  -  []  368.28 297.12 0 top
NOREF#1628  -  []  229.21 243.09 0 top
NOREF#1629  -  []  177.33 214.75 90 top
NOREF#1630  -  []  384.36 131.89 0 top
NOREF#1631  -  []  229.05 271.67 0 top
NOREF#1632  -  []  260.83 234.63 90 top
NOREF#1633  -  []  383.09 241.11 0 top
NOREF#1634  -  []  319.15 288.86 0 top
NOREF#1635  -  []  94.68 234.24 0 top
NOREF#1636  -  []  332.51 265.55 0 top
NOREF#1637  -  []  306.85 211.67 0 top
NOREF#1638  -  []  272.25 241.05 90 top
NOREF#1639  -  []  192.47 164.3 90 top
NOREF#1640  -  []  352.25 189.82 0 top
NOREF#1641  -  []  392.24 193.43 90 top
NOREF#1642  -  []  336.45 224.72 0 top
NOREF#1643  -  []  271.34 249.5 0 top
NOREF#1644  -  []  332.83 205.86 90 top
NOREF#1645  -  []  201.23 214 90 top
NOREF#1646  -  []  389.7 209.36 0 top
NOREF#1647  -  []  342.63 296.86 0 top
NOREF#1648  -  []  200.98 258.7 90 top
NOREF#1649  -  []  122.19 214.79 0 top
NOREF#1650  -  []  221.56 190.49 0 top
NOREF#1651  -  []  309.21 186.34 0 top
NOREF#1652  -  []  192.57 160.9 90 top
NOREF#1653  -  []  315.7 296.86 0 top
NOREF#1654  -  []  327.25 264.35 90 top
NOREF#1655  -  []  194.09 242.18 90 top
NOREF#1656  -  []  327.89 204.35 90 top
NOREF#1657  -  []  283.21 282 0 top
NOREF#1658  -  []  273.59 272.15 90 top
NOREF#1659  -  []  184.89 186.02 90 top
NOREF#1660  -  []  461.96 210.36 0 top
NOREF#1661  -  []  473.7 176.22 90 top
NOREF#1662  -  []  201.49 173.11 0 top
NOREF#1663  -  []  182.57 158.5 90 top
NOREF#1664  -  []  201.23 219.75 90 top
NOREF#1665  -  []  253.53 140.14 0 top
NOREF#1666  -  []  218.13 214.06 90 top
NOREF#1667  -  []  384.17 163.39 90 top
NOREF#1668  -  []  367.48 242.38 90 top
NOREF#1669  -  []  400.85 297.12 0 top
NOREF#1670  -  []  272.24 189.18 90 top
NOREF#1671  -  []  327.25 205.55 0 top
NOREF#1672  -  []  385.19 297.12 0 top
NOREF#1673  -  []  301.95 290.13 90 top
NOREF#1674  -  []  295.96 177.06 0 top
NOREF#1675  -  []  201.49 161 90 top
NOREF#1676  -  []  295.96 237.06 0 top
NOREF#1677  -  []  201.23 231.27 90 top
NOREF#1678  -  []  219.81 273.69 90 top
NOREF#1679  -  []  175.7 222.95 90 top
NOREF#1680  -  []  166.06 135.19 90 top
NOREF#1681  -  []  66.26 287.84 90 top
NOREF#1682  -  []  379.01 288.67 90 top
NOREF#1683  -  []  262.04 224.74 0 top
NOREF#1684  -  []  315.82 129.74 0 top
NOREF#1685  -  []  309.21 246.34 0 top
NOREF#1686  -  []  230.43 183.09 0 top
NOREF#1687  -  []  201.23 217.55 90 top
NOREF#1688  -  []  192.47 195.52 90 top
NOREF#1689  -  []  277.17 288.86 0 top
NOREF#1690  -  []  406.65 271.21 90 top
NOREF#1691  -  []  338.2 186.67 0 top
NOREF#1692  -  []  331.05 204.65 90 top
NOREF#1693  -  []  317.57 209.63 90 top
NOREF#1694  -  []  410.78 131.89 0 top
NOREF#1695  -  []  400.79 154.88 0 top
NOREF#1696  -  []  310.73 183.41 0 top
NOREF#1697  -  []  209.33 201.79 90 top
NOREF#1698  -  []  279.27 296.86 0 top
NOREF#1699  -  []  199.84 148.65 90 top
NOREF#1700  -  []  247.25 264.35 90 top
NOREF#1701  -  []  415.61 179.97 0 top
NOREF#1702  -  []  201.49 174.46 90 top
NOREF#1703  -  []  192.47 202.99 90 top
NOREF#1704  -  []  175.8 256.4 90 top
NOREF#1705  -  []  272.24 184.86 90 top
NOREF#1706  -  []  412.62 289.12 0 top
NOREF#1707  -  []  471.21 168.33 0 top
NOREF#1708  -  []  412.37 257.37 0 top
NOREF#1709  -  []  518.38 257.36 90 top
NOREF#1710  -  []  461.96 174.55 0 top
NOREF#1711  -  []  184.89 172.56 90 top
NOREF#1712  -  []  378.33 217.11 0 top
NOREF#1713  -  []  167.7 174.46 90 top
NOREF#1714  -  []  352.55 189.5 0 top
NOREF#1715  -  []  188.08 289.11 90 top
NOREF#1716  -  []  378.33 224.6 90 top
NOREF#1717  -  []  352.24 241.05 90 top
NOREF#1718  -  []  310.73 243.41 0 top
NOREF#1719  -  []  412.62 273.37 0 top
NOREF#1720  -  []  309.51 193.69 0 top
NOREF#1721  -  []  107.02 171.57 0 top
NOREF#1722  -  []  471.21 219.38 0 top
NOREF#1723  -  []  234.33 228.13 90 top
NOREF#1724  -  []  395.2 265.37 0 top
NOREF#1725  -  []  304.61 131.64 0 top
NOREF#1726  -  []  199.84 162.12 90 top
NOREF#1727  -  []  283.25 147.43 90 top
NOREF#1728  -  []  334.61 265.86 90 top
NOREF#1729  -  []  398.53 144.98 90 top
NOREF#1730  -  []  310.73 189.2 0 top
NOREF#1731  -  []  343.63 223.82 90 top
NOREF#1732  -  []  310.43 253.37 90 top
NOREF#1733  -  []  330.74 164.74 0 top
NOREF#1734  -  []  259.45 288.86 90 top
NOREF#1735  -  []  448.94 273.87 90 top
NOREF#1736  -  []  218.13 214.06 0 top
NOREF#1737  -  []  199.08 254 90 top
NOREF#1738  -  []  263.2 232.26 90 top
NOREF#1739  -  []  182.57 212.85 0 top
NOREF#1740  -  []  419.9 272.92 90 top
NOREF#1741  -  []  334.81 296.86 0 top
NOREF#1742  -  []  376.15 192.88 90 top
NOREF#1743  -  []  263.71 288.86 0 top
NOREF#1744  -  []  451.68 239.34 0 top
NOREF#1745  -  []  332.83 264.65 90 top
NOREF#1746  -  []  459.24 175.86 90 top
NOREF#1747  -  []  343.31 224.74 0 top
NOREF#1748  -  []  459.28 236.14 0 top
NOREF#1749  -  []  410.84 180.15 90 top
NOREF#1750  -  []  261.82 290.13 90 top
NOREF#1751  -  []  261.16 135.74 90 top
NOREF#1752  -  []  479.44 195.66 0 top
NOREF#1753  -  []  167.7 159.65 90 top
NOREF#1754  -  []  230.43 246.34 0 top
NOREF#1755  -  []  319.15 296.86 0 top
NOREF#1756  -  []  459.28 183.57 0 top
NOREF#1757  -  []  167.7 159.65 0 top
NOREF#1758  -  []  262.09 143.19 0 top
NOREF#1759  -  []  424.05 163.64 90 top
NOREF#1760  -  []  329.28 225.04 90 top
NOREF#1761  -  []  463.61 214.96 0 top
NOREF#1762  -  []  449.99 174.46 0 top
NOREF#1763  -  []  259.59 145.09 0 top
NOREF#1764  -  []  252.51 265.56 0 top
NOREF#1765  -  []  272.25 185.5 0 top
NOREF#1766  -  []  201.23 214 0 top
NOREF#1767  -  []  351.58 288.86 0 top
NOREF#1768  -  []  263.31 164.72 0 top
NOREF#1769  -  []  120.21 178.64 0 top
NOREF#1770  -  []  221.56 250.49 0 top
NOREF#1771  -  []  385.61 208.66 90 top
NOREF#1772  -  []  383.09 273.11 0 top
NOREF#1773  -  []  473.7 219.66 90 top
NOREF#1774  -  []  263.31 224.72 0 top
NOREF#1775  -  []  272.24 249.18 90 top
NOREF#1776  -  []  165.8 171.96 90 top
NOREF#1777  -  []  194.09 187.32 90 top
NOREF#1778  -  []  309.21 188.88 0 top
NOREF#1779  -  []  339.33 205.56 90 top
NOREF#1780  -  []  201.49 163.2 90 top
NOREF#1781  -  []  392.66 192.88 90 top
NOREF#1782  -  []  199.33 212.85 0 top
NOREF#1783  -  []  165.8 254 90 top
NOREF#1784  -  []  410.52 241.11 0 top
NOREF#1785  -  []  419.47 273.37 90 top
NOREF#1786  -  []  343.95 163.52 90 top
NOREF#1787  -  []  101.82 287.84 90 top
NOREF#1788  -  []  167.7 258.7 90 top
NOREF#1789  -  []  410.27 257.37 0 top
NOREF#1790  -  []  300.01 288.41 90 top
NOREF#1791  -  []  414.82 249.11 0 top
NOREF#1792  -  []  369.63 289.12 0 top
NOREF#1793  -  []  317.83 257.63 0 top
NOREF#1794  -  []  167.7 138.47 90 top
NOREF#1795  -  []  321.82 167.13 90 top
NOREF#1796  -  []  283.91 273.37 90 top
NOREF#1797  -  []  403.99 180.15 0 top
NOREF#1798  -  []  106.76 222.88 0 top
NOREF#1799  -  []  177.33 173.86 90 top
NOREF#1800  -  []  118.7 188.08 0 top
NOREF#1801  -  []  334.61 205.86 90 top
NOREF#1802  -  []  254.61 264.65 90 top
NOREF#1803  -  []  218.13 274.06 90 top
NOREF#1804  -  []  253.4 204.35 90 top
NOREF#1805  -  []  310.73 247.93 0 top
NOREF#1806  -  []  229.21 248.88 0 top
NOREF#1807  -  []  396.55 273.11 0 top
NOREF#1808  -  []  106.36 190.55 0 top
NOREF#1809  -  []  346.27 129.42 90 top
NOREF#1810  -  []  413.71 178.82 90 top
NOREF#1811  -  []  331.05 265.86 90 top
NOREF#1812  -  []  250.17 163.82 90 top
NOREF#1813  -  []  229.21 187.61 0 top
NOREF#1814  -  []  119.95 222.33 0 top
NOREF#1815  -  []  167.7 200.54 0 top
NOREF#1816  -  []  182.57 199.39 90 top
NOREF#1817  -  []  416.03 179.42 90 top
NOREF#1818  -  []  165.8 171.96 0 top
NOREF#1819  -  []  201.23 233.47 90 top
NOREF#1820  -  []  404.24 154.88 0 top
NOREF#1821  -  []  330.18 242.88 0 top
NOREF#1822  -  []  396.55 289.12 0 top
NOREF#1823  -  []  247.78 132.14 90 top
NOREF#1824  -  []  310.43 187.61 90 top
NOREF#1825  -  []  253.72 204.65 90 top
NOREF#1826  -  []  199.59 171.96 0 top
NOREF#1827  -  []  112.16 238.84 0 top
NOREF#1828  -  []  230.43 186.34 90 top
NOREF#1829  -  []  420.37 255.47 90 top
NOREF#1830  -  []  408.02 271.47 0 top
NOREF#1831  -  []  332.83 204.65 90 top
NOREF#1832  -  []  304.82 146.05 0 top
NOREF#1833  -  []  300.36 248.49 0 top
NOREF#1834  -  []  201.49 178.86 90 top
NOREF#1835  -  []  414.25 154.88 0 top
NOREF#1836  -  []  329.6 164.74 90 top
NOREF#1837  -  []  398.65 233.11 0 top
NOREF#1838  -  []  405.93 272.66 90 top
NOREF#1839  -  []  249.28 225.04 90 top
NOREF#1840  -  []  417.87 257.37 0 top
NOREF#1841  -  []  396.55 257.37 0 top
NOREF#1842  -  []  272.55 182.64 0 top
NOREF#1843  -  []  259.33 205.56 90 top
NOREF#1844  -  []  399.99 164.91 90 top
NOREF#1845  -  []  373.32 164.66 90 top
NOREF#1846  -  []  251.62 265.56 90 top
NOREF#1847  -  []  201.49 165.4 90 top
NOREF#1848  -  []  400.85 281.11 0 top
NOREF#1849  -  []  108.01 195.15 0 top
NOREF#1850  -  []  483.04 195.66 0 top
NOREF#1851  -  []  310.43 248.88 90 top
NOREF#1852  -  []  309.12 154.05 0 top
NOREF#1853  -  []  317.98 223.82 90 top
NOREF#1854  -  []  305.83 264.31 0 top
NOREF#1855  -  []  377.48 289.17 90 top
NOREF#1856  -  []  327.27 131.64 90 top
NOREF#1857  -  []  112.41 214.71 0 top
NOREF#1858  -  []  336.45 164.72 0 top
NOREF#1859  -  []  182.57 254 90 top
NOREF#1860  -  []  459.28 168.33 0 top
NOREF#1861  -  []  177.33 146.68 90 top
NOREF#1862  -  []  272.24 249.18 90 top
NOREF#1863  -  []  252.43 132.14 0 top
NOREF#1864  -  []  398.65 281.11 0 top
NOREF#1865  -  []  463.61 214.96 0 top
NOREF#1866  -  []  352.55 185.18 0 top
NOREF#1867  -  []  116.01 222.33 0 top
NOREF#1868  -  []  230.73 246.66 0 top
NOREF#1869  -  []  352.24 244.86 90 top
NOREF#1870  -  []  249.28 165.04 90 top
NOREF#1871  -  []  117.01 234.24 90 top
NOREF#1872  -  []  339.33 204.35 90 top
NOREF#1873  -  []  106.03 217.88 90 top
NOREF#1874  -  []  385.36 194.18 90 top
NOREF#1875  -  []  351.04 242.96 0 top
NOREF#1876  -  []  201.23 247.18 90 top
NOREF#1877  -  []  348.28 296.86 0 top
NOREF#1878  -  []  462.06 291.28 90 top
NOREF#1879  -  []  390.59 195.9 90 top
NOREF#1880  -  []  127.95 195.15 0 top
NOREF#1881  -  []  229.51 186.66 0 top
NOREF#1882  -  []  236.27 289.16 90 top
NOREF#1883  -  []  184.47 161 90 top
NOREF#1884  -  []  369.63 273.11 0 top
NOREF#1885  -  []  300.36 177.06 0 top
NOREF#1886  -  []  247.25 205.55 0 top
NOREF#1887  -  []  383.73 198.08 90 top
NOREF#1888  -  []  299.81 273.69 90 top
NOREF#1889  -  []  393.19 255.21 90 top
NOREF#1890  -  []  329.6 163.52 90 top
NOREF#1891  -  []  423.45 146.93 90 top
NOREF#1892  -  []  419.9 272.82 90 top
NOREF#1893  -  []  252.51 205.56 0 top
NOREF#1894  -  []  108.01 222.33 0 top
NOREF#1895  -  []  475.04 195.66 0 top
NOREF#1896  -  []  324.9 288.91 90 top
NOREF#1897  -  []  392.47 256.56 90 top
NOREF#1898  -  []  293.31 272.1 0 top
NOREF#1899  -  []  472.86 217.98 90 top
NOREF#1900  -  []  166.06 175.58 90 top
NOREF#1901  -  []  396.03 146.88 0 top
NOREF#1902  -  []  332.61 288.86 0 top
NOREF#1903  -  []  352.25 242.96 0 top
NOREF#1904  -  []  110.47 178.64 0 top
NOREF#1905  -  []  273.24 272.1 0 top
NOREF#1906  -  []  266.74 272.1 0 top
NOREF#1907  -  []  257.09 224.74 90 top
NOREF#1908  -  []  328.33 247.93 0 top
NOREF#1909  -  []  230.83 224.63 0 top
NOREF#1910  -  []  310.43 188.88 90 top
NOREF#1911  -  []  404.4 241.16 90 top
NOREF#1912  -  []  252.83 265.86 90 top
NOREF#1913  -  []  317.66 164.74 0 top
NOREF#1914  -  []  411.52 146.33 90 top
NOREF#1915  -  []  168.13 186.02 90 top
NOREF#1916  -  []  128.24 171.1 0 top
NOREF#1917  -  []  463.61 179.15 0 top
NOREF#1918  -  []  388.43 146.88 0 top
NOREF#1919  -  []  127.3 228.02 90 top
NOREF#1920  -  []  409.99 146.93 90 top
NOREF#1921  -  []  351.04 244.23 0 top
NOREF#1922  -  []  115.61 191.95 90 top
NOREF#1923  -  []  381.2 290.39 90 top
NOREF#1924  -  []  415.6 146.88 0 top
NOREF#1925  -  []  118.33 289.48 90 top
NOREF#1926  -  []  410.78 131.89 0 top
NOREF#1927  -  []  209.23 218.65 90 top
NOREF#1928  -  []  329.28 163.82 90 top
NOREF#1929  -  []  390.94 241.16 90 top
NOREF#1930  -  []  175.8 201.79 90 top
NOREF#1931  -  []  340.83 234.63 90 top
NOREF#1932  -  []  165.8 131.57 0 top
NOREF#1933  -  []  376.23 209.11 0 top
NOREF#1934  -  []  375.73 199.18 90 top
NOREF#1935  -  []  326 288.86 90 top
NOREF#1936  -  []  184.47 192.32 90 top
NOREF#1937  -  []  177.33 255.9 90 top
NOREF#1938  -  []  405.42 131.94 90 top
NOREF#1939  -  []  216.96 252.14 0 top
NOREF#1940  -  []  272.25 243.59 90 top
NOREF#1941  -  []  313.94 286.96 90 top
NOREF#1942  -  []  270.04 280.1 0 top
NOREF#1943  -  []  184.47 173.11 90 top
NOREF#1944  -  []  166.06 148.4 90 top
NOREF#1945  -  []  399.07 208.81 90 top
NOREF#1946  -  []  413.51 207.71 90 top
NOREF#1947  -  []  263.95 164.74 90 top
NOREF#1948  -  []  201.49 178.86 90 top
NOREF#1949  -  []  396.55 225.11 0 top
NOREF#1950  -  []  383.09 273.11 0 top
NOREF#1951  -  []  251.06 163.82 90 top
NOREF#1952  -  []  218.16 188.49 0 top
NOREF#1953  -  []  379.73 287.22 90 top
NOREF#1954  -  []  462.06 274.77 90 top
NOREF#1955  -  []  303.26 139.64 0 top
NOREF#1956  -  []  119.99 214.79 0 top
NOREF#1957  -  []  394.05 287.22 0 top
NOREF#1958  -  []  245.15 288.66 90 top
NOREF#1959  -  []  373.73 207.21 0 top
NOREF#1960  -  []  400.24 198.08 90 top
NOREF#1961  -  []  219.76 297.18 0 top
NOREF#1962  -  []  218.13 274.06 0 top
NOREF#1963  -  []  271.34 249.5 0 top
NOREF#1964  -  []  284.77 288.86 0 top
NOREF#1965  -  []  417.7 154.88 0 top
NOREF#1966  -  []  192.57 228.97 90 top
NOREF#1967  -  []  398.65 289.12 0 top
NOREF#1968  -  []  272.25 184.86 90 top
